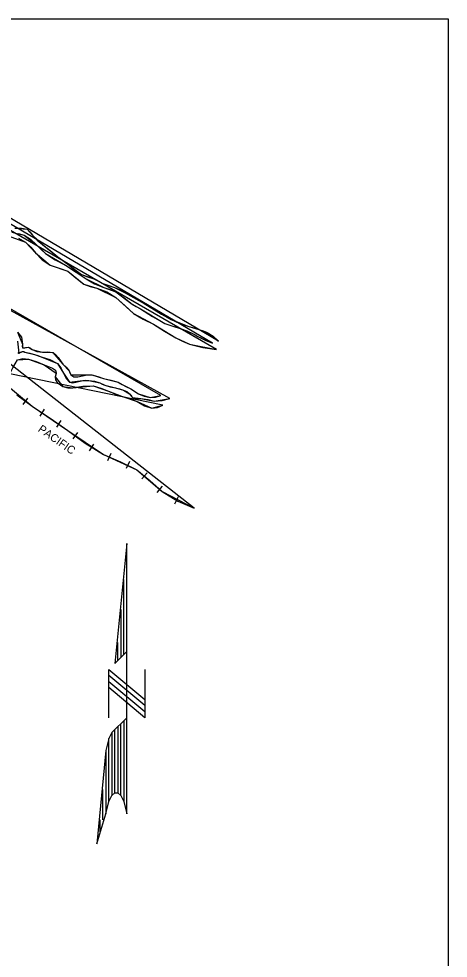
# Model space of a CAD drawing. Extents: x 5.01 to 9.58, y 0.27 to 3.39.
# Drawn here: x 8.957 to 9.58, y 1.858 to 3.219 of the extents above; entities that cross this region are included whole.
import ezdxf

# ---------------------------------------------------------------- set-up
doc = ezdxf.new("R2010")
doc.units = 0
for name, color, linetype in [('MO_001_NOSHOW', 7, 'Continuous'), ('MO_001_VIEW_99', 7, 'Continuous'), ('MO_001_VIEW_PV', 7, 'Continuous')]:
    doc.layers.add(name, color=color, linetype=linetype)

msp = doc.modelspace()

# ---------------------------------------------------------------- linework, layer by layer
at = {"layer": 'MO_001_NOSHOW'}
for points in [[(8.9471, 2.9102), (8.9649, 2.9058), (8.9827, 2.8924), (8.996, 2.8791), (9.0249, 2.8625), (9.0404, 2.8525), (9.0548, 2.8425), (9.0804, 2.8303), (9.0981, 2.8236), (9.1215, 2.8058), (9.1337, 2.7992), (9.1692, 2.7781), (9.1925, 2.7703), (9.2092, 2.7636), (9.217, 2.7592), (9.2381, 2.7492), (8.7977, 3.0087)], [(8.9516, 2.9158), (8.9693, 2.9147), (8.9771, 2.9058), (8.9915, 2.8924), (9.0137, 2.8747), (9.0304, 2.8625), (9.0482, 2.8491), (9.0659, 2.8425), (9.0793, 2.8358), (9.0959, 2.8303), (9.1115, 2.8225), (9.1392, 2.8069), (9.1503, 2.8003), (9.1781, 2.7836), (9.2036, 2.7736), (9.2181, 2.7692), (9.2303, 2.7647), (9.2469, 2.7525), (8.8022, 3.0147)], [(8.9556, 2.7524), (8.9574, 2.7349), (8.9626, 2.7375), (8.9661, 2.7366), (8.9802, 2.7331), (8.9898, 2.7296), (9.0135, 2.72), (9.0222, 2.7059), (9.031, 2.6928), (9.0503, 2.6954), (9.059, 2.6954), (9.0748, 2.6919), (9.0818, 2.6884), (9.0976, 2.6849), (9.109, 2.6814), (9.1177, 2.6761), (9.1212, 2.6718), (9.1221, 2.6709), (9.1344, 2.6691), (9.1536, 2.6656), (9.1764, 2.6691), (8.7237, 2.9187)], [(8.9556, 2.7655), (8.9626, 2.748), (8.9626, 2.7427), (8.9714, 2.7436), (8.9767, 2.7401), (8.9916, 2.7366), (9.0065, 2.7357), (9.0213, 2.7191), (9.0301, 2.7094), (9.0327, 2.7033), (9.0564, 2.7033), (9.0634, 2.7033), (9.0801, 2.6981), (9.1011, 2.6928), (9.1072, 2.6893), (9.1195, 2.6832), (9.1309, 2.6761), (9.1475, 2.6709), (9.1633, 2.6735), (8.7272, 2.9241)]]:
    msp.add_lwpolyline(points, dxfattribs=at)
for points in [[(8.7919, 3.001), (8.8172, 2.9868), (8.8316, 2.968), (8.8494, 2.9569), (8.8672, 2.9491), (8.8894, 2.9313), (8.9216, 2.9124), (8.9671, 2.8958), (8.9815, 2.8802), (9.0026, 2.8625), (9.0282, 2.8536), (9.0515, 2.8347), (9.0704, 2.8292), (9.0981, 2.8158), (9.1237, 2.7925), (9.1526, 2.777), (9.1848, 2.757), (9.2047, 2.7481), (9.2436, 2.7403)], [(8.7117, 2.9016), (8.7327, 2.8893), (8.7696, 2.8653), (8.8048, 2.8338), (8.8492, 2.795), (8.8991, 2.7432), (8.9342, 2.6933), (8.9767, 2.6582), (9.0285, 2.623), (9.0803, 2.5879), (9.1284, 2.5657), (9.1653, 2.5343), (9.2116, 2.5103)], [(8.9442, 2.7051), (8.9486, 2.7138), (8.9556, 2.7252), (8.9714, 2.7261), (8.9942, 2.7182), (9.0117, 2.7059), (9.01, 2.7007), (9.0213, 2.6867), (9.0354, 2.6849), (9.0652, 2.6875), (9.0871, 2.6797), (9.1063, 2.6727), (9.1291, 2.6648), (9.1502, 2.6551), (9.1659, 2.6595)]]:
    msp.add_lwpolyline(points, close=True, dxfattribs=at)
at = {"layer": 'MO_001_VIEW_99'}
for p, q in [((5.014, 3.2194), (9.5796, 3.2194)), ((9.5796, 3.2194), (9.5796, 0.3206))]:
    msp.add_line(p, q, dxfattribs=at)
at = {"layer": 'MO_001_VIEW_PV'}
for p, q in [((8.97, 2.6699), (8.9634, 2.6604)), ((8.9941, 2.6536), (8.9876, 2.6438)), ((9.0184, 2.6373), (9.0119, 2.6276)), ((9.0423, 2.6201), (9.0354, 2.6107)), ((9.0658, 2.6031), (9.0593, 2.5933)), ((9.0906, 2.5896), (9.086, 2.5789)), ((9.1177, 2.5782), (9.1128, 2.5676)), ((9.1435, 2.5615), (9.1358, 2.5527)), ((9.1651, 2.542), (9.1576, 2.533)), ((9.1884, 2.5267), (9.1831, 2.5163)), ((9.1094, 2.2982), (9.1094, 2.4069)), ((9.105, 2.3634), (9.105, 2.2938)), ((9.1007, 2.2895), (9.1007, 2.3156)), ((9.1398, 2.2242), (9.0876, 2.2677)), ((9.0876, 2.259), (9.1398, 2.2155)), ((9.1007, 2.1938), (9.1007, 2.0981)), ((9.105, 2.0938), (9.105, 2.1981)), ((9.1094, 2.2025), (9.1094, 2.0851)), ((9.092, 2.1851), (9.092, 2.0938)), ((9.0963, 2.0981), (9.0963, 2.1895)), ((9.0876, 2.0851), (9.0876, 2.1764)), ((9.0833, 2.159), (9.0833, 2.0677)), ((9.0789, 2.059), (9.0789, 2.1025)), ((9.0746, 2.059), (9.0746, 2.0416))]:
    msp.add_line(p, q, dxfattribs=at)
for points in [[(8.9516, 2.9158), (8.961, 2.916), (8.9693, 2.9147), (8.9735, 2.9108), (8.9771, 2.9058), (8.984, 2.8986), (8.9915, 2.8924), (9.0026, 2.8835), (9.0137, 2.8747), (9.0221, 2.8687), (9.0304, 2.8625), (9.039, 2.8553), (9.0482, 2.8491), (9.057, 2.8457), (9.0659, 2.8425), (9.0726, 2.8391), (9.0793, 2.8358), (9.0876, 2.833), (9.0959, 2.8303), (9.1038, 2.8267), (9.1115, 2.8225), (9.1254, 2.8148), (9.1392, 2.8069), (9.1448, 2.8037), (9.1503, 2.8003), (9.164, 2.7916), (9.1781, 2.7836), (9.1907, 2.7781), (9.2036, 2.7736), (9.2108, 2.7714), (9.2181, 2.7692), (9.2243, 2.7672), (9.2303, 2.7647), (9.2391, 2.7594), (9.2469, 2.7525)], [(8.9562, 2.9084), (8.9649, 2.9058), (8.9743, 2.9001), (8.9827, 2.8924), (8.9892, 2.8855), (8.996, 2.8791), (9.0099, 2.8702), (9.0249, 2.8625), (9.0328, 2.8577), (9.0404, 2.8525), (9.0476, 2.8474), (9.0548, 2.8425), (9.0672, 2.8356), (9.0804, 2.8303), (9.0895, 2.8273), (9.0981, 2.8236), (9.1099, 2.815), (9.1215, 2.8058), (9.1275, 2.8024), (9.1337, 2.7992), (9.1513, 2.7882), (9.1692, 2.7781), (9.1807, 2.7739), (9.1925, 2.7703), (9.201, 2.7673), (9.2092, 2.7636), (9.2131, 2.7614), (9.217, 2.7592), (9.2274, 2.7539), (9.2381, 2.7492)], [(8.957, 2.9017), (8.9671, 2.8958), (8.9746, 2.8885), (8.9815, 2.8802), (8.9913, 2.8701), (9.0026, 2.8625), (9.0156, 2.8583), (9.0282, 2.8536), (9.0398, 2.844), (9.0515, 2.8347), (9.0606, 2.8314), (9.0704, 2.8292), (9.085, 2.8239), (9.0981, 2.8158), (9.1109, 2.804), (9.1237, 2.7925), (9.1378, 2.7843), (9.1526, 2.777), (9.1687, 2.767), (9.1848, 2.757), (9.1946, 2.7521), (9.2047, 2.7481), (9.2239, 2.7429), (9.2436, 2.7403)], [(8.9556, 2.7655), (8.9612, 2.7582), (8.9626, 2.748), (8.9623, 2.7449), (8.9626, 2.7427), (8.9663, 2.7428), (8.9714, 2.7436), (8.9742, 2.7423), (8.9767, 2.7401), (8.9836, 2.7371), (8.9916, 2.7366), (8.9995, 2.7369), (9.0065, 2.7357), (9.0106, 2.7328), (9.0142, 2.7285), (9.0213, 2.7191), (9.0262, 2.7145), (9.0301, 2.7094), (9.0314, 2.7062), (9.0327, 2.7033), (9.0369, 2.7007), (9.0429, 2.7007), (9.0564, 2.7033), (9.06, 2.7036), (9.0634, 2.7033), (9.0717, 2.701), (9.0801, 2.6981), (9.0908, 2.6958), (9.1011, 2.6928), (9.1042, 2.6911), (9.1072, 2.6893), (9.1134, 2.6862), (9.1195, 2.6832), (9.1252, 2.6797), (9.1309, 2.6761), (9.1389, 2.6726), (9.1475, 2.6709), (9.1556, 2.6714), (9.1633, 2.6735)], [(8.9558, 2.7361), (8.9574, 2.7349), (8.9597, 2.7363), (8.9626, 2.7375), (8.9644, 2.7373), (8.9661, 2.7366), (8.9732, 2.7347), (8.9802, 2.7331), (8.985, 2.7314), (8.9898, 2.7296), (9.0025, 2.7257), (9.0135, 2.72), (9.0184, 2.7138), (9.0222, 2.7059), (9.026, 2.698), (9.031, 2.6928), (9.0352, 2.6921), (9.04, 2.6929), (9.0503, 2.6954), (9.0547, 2.6957), (9.059, 2.6954), (9.0671, 2.6943), (9.0748, 2.6919), (9.0783, 2.6901), (9.0818, 2.6884), (9.0896, 2.6863), (9.0976, 2.6849), (9.1033, 2.6834), (9.109, 2.6814), (9.1137, 2.6792), (9.1177, 2.6761), (9.1195, 2.674), (9.1212, 2.6718), (9.1217, 2.6713), (9.1221, 2.6709), (9.1278, 2.6691), (9.1344, 2.6691), (9.1442, 2.6676), (9.1536, 2.6656), (9.1651, 2.6662), (9.1764, 2.6691)], [(8.9556, 2.7252), (8.963, 2.7271), (8.9714, 2.7261), (8.9825, 2.7227), (8.9942, 2.7182), (9.0064, 2.7134), (9.0106, 2.7101), (9.0117, 2.7059), (9.0109, 2.7034), (9.01, 2.7007), (9.0104, 2.6964), (9.0129, 2.6924), (9.0213, 2.6867), (9.0284, 2.6849), (9.0354, 2.6849), (9.0503, 2.687), (9.0652, 2.6875), (9.0762, 2.6844), (9.0871, 2.6797), (9.0966, 2.6758), (9.1063, 2.6727), (9.1179, 2.6693), (9.1291, 2.6648), (9.1395, 2.6588), (9.1502, 2.6551), (9.1582, 2.6562), (9.1659, 2.6595)], [(8.9543, 2.6745), (8.9767, 2.6582), (9.0028, 2.6408), (9.0285, 2.623), (9.0537, 2.6043), (9.0803, 2.5879), (9.1048, 2.5775), (9.1284, 2.5657), (9.147, 2.5504), (9.1653, 2.5343), (9.1876, 2.5206), (9.2116, 2.5103)], [(9.1137, 2.2068), (9.092, 2.1851), (9.0876, 2.1764), (9.0833, 2.159), (9.0702, 2.0242), (9.0833, 2.0677), (9.0876, 2.0851), (9.092, 2.0938), (9.0963, 2.0981), (9.1007, 2.0981), (9.105, 2.0938), (9.1094, 2.0851), (9.1137, 2.0677), (9.1137, 2.459), (9.0963, 2.2851), (9.1137, 2.3025)], [(9.0876, 2.2068), (9.0876, 2.2764), (9.1398, 2.2329)], [(9.1398, 2.2764), (9.1398, 2.2068), (9.0876, 2.2503)]]:
    msp.add_lwpolyline(points, dxfattribs=at)

# ---------------------------------------------------------------- texts
msp.add_text('PACIFIC', height=0.01159, rotation=325, dxfattribs=at).set_placement((8.9842, 2.6225))

doc.saveas('drawing.dxf')
